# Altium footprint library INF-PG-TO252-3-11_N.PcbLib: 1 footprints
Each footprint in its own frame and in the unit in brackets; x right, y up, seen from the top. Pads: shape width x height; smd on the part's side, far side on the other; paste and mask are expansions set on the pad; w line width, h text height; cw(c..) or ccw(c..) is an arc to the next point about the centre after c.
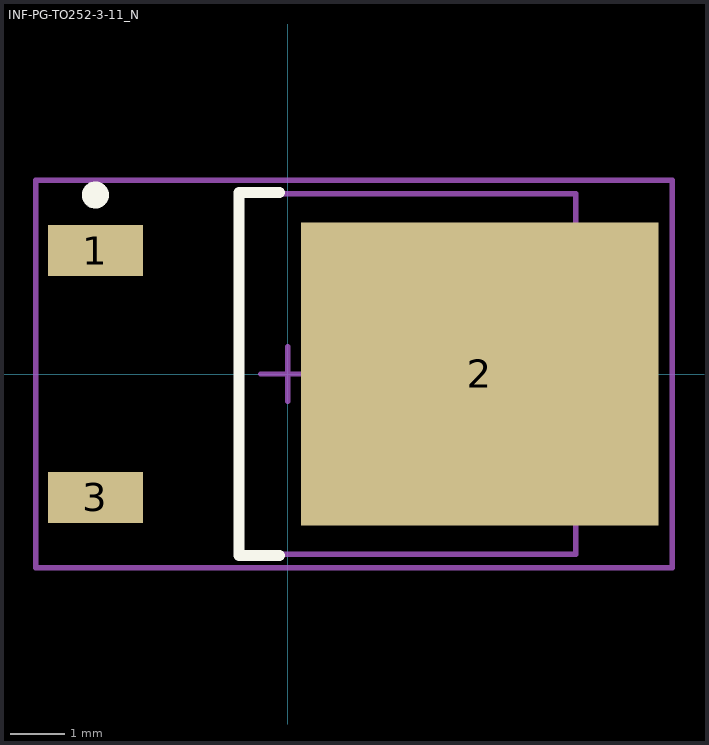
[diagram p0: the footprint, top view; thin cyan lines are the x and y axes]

## INF-PG-TO252-3-11_N [mm] "DPAK, 3-Leads, Body 6.5x6.12mm, Pitch 2.28mm, IPC Medium Density"
height 2.35
pads (3):
  rect 1.75x0.95 smd paste+0 mask+0: 1(-3.55,2.28) 3(-3.55,-2.28)
  rect 6.6x5.6 smd paste+0 mask+0: 2(3.55,0)
Top Overlay:
  circle w0.25: c-3.55,3.305 r0.125
  lines w0.2: -0.15,-3.35 -0.9,-3.35 -0.9,3.35 -0.15,3.35
Mechanical 3:
  text ".DESIGNATOR" at 0,0 h1.2
Mechanical 13:
  lines w0.1: -0.9,-3.325 5.32,-3.325 5.32,3.325 -0.9,3.325 -0.9,-3.325
Mechanical 15:
  lines w0.1: -0.5,0 0.5,0 ; 0,-0.5 0,0.5 ; -4.65,-3.58 7.1,-3.58 7.1,3.58 -4.65,3.58 -4.65,-3.58
3D body: height 2.36, standoff 0, extent -3.72,-3.25 6.26,3.25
